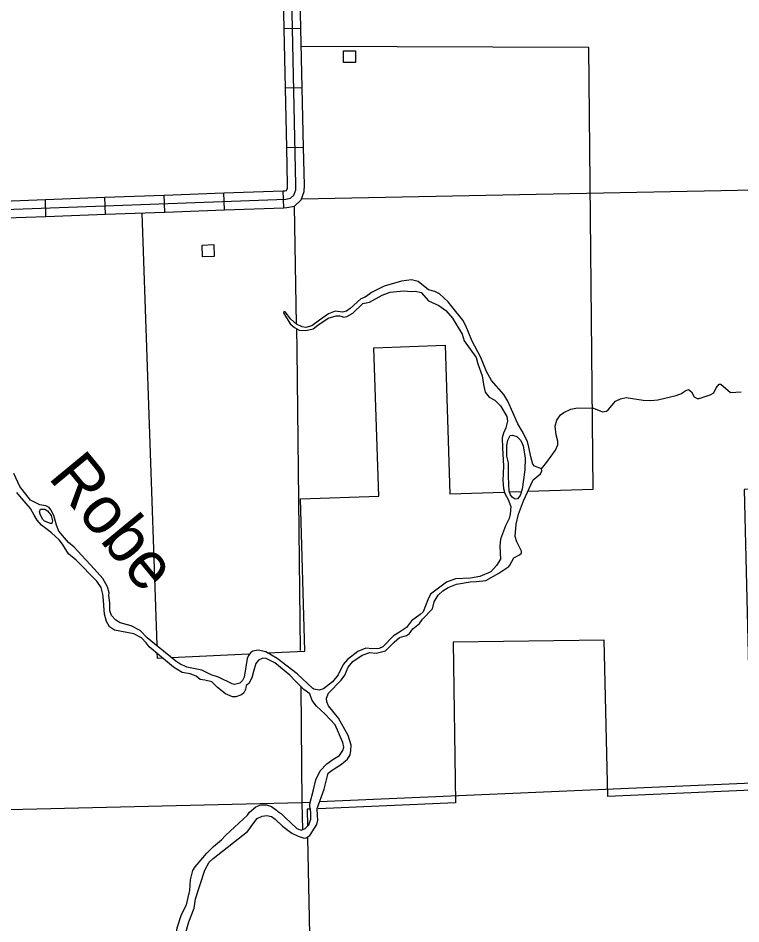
# Model space of a CAD drawing. Extents: x 1084508 to 1142749, y 1057638 to 1093403.
# Drawn here: x 1090220 to 1092233, y 1079943 to 1082464 of the extents above; entities that cross this region are included whole.
import ezdxf

# ---------------------------------------------------------------- set-up
doc = ezdxf.new("R2010")
doc.units = 0
for name, color, linetype in [('Level 32', 7, 'Continuous'), ('Level 35', 7, 'Continuous'), ('Level 5', 7, 'Continuous'), ('Level 56', 7, 'Continuous'), ('Level 7', 7, 'Continuous')]:
    doc.layers.add(name, color=color, linetype=linetype)

msp = doc.modelspace()

# ---------------------------------------------------------------- linework, layer by layer
at = {"layer": 'Level 32'}
for p, q in [((1091008, 1082435.6), (1090961, 1082434.6)), ((1091011.6, 1082270), (1090964.6, 1082268.9)), ((1091015.2, 1082104.3), (1090968.2, 1082103.2)), ((1090297.8, 1081912.2), (1090296.1, 1081959.3)), ((1090463.4, 1081918.2), (1090461.7, 1081965.3)), ((1090629, 1081924.3), (1090627.3, 1081971.3)), ((1090794.7, 1081930.3), (1090792.9, 1081977.4)), ((1090960.3, 1081936.3), (1090958.6, 1081983.4))]:
    msp.add_line(p, q, dxfattribs=at)
for points in [[(1090994, 1081999.7), (1090982.6, 1082523.3), (1090967.9, 1082952.3), (1090978.3, 1083028.7), (1090986.1, 1083044.5), (1091035.2, 1083088.7), (1091053.7, 1083101.5)], [(1090961, 1082434.6), (1090959, 1082522.7), (1090956.4, 1082600)], [(1091008, 1082435.6), (1091006.1, 1082524), (1091003.5, 1082601.6)], [(1090964.6, 1082268.9), (1090961, 1082434.6)], [(1091011.6, 1082270), (1091008, 1082435.6)], [(1090968.2, 1082103.2), (1090964.6, 1082268.9)], [(1091015.2, 1082104.3), (1091011.6, 1082270)], [(1090958.6, 1081983.4), (1090963.4, 1081983.6), (1090967.6, 1081984.4), (1090967.9, 1081984.7), (1090970, 1081990.6), (1090970.4, 1082000), (1090968.2, 1082103.2)], [(1090960.3, 1081936.3), (1090968.9, 1081936.7), (1090990.3, 1081941), (1091008.7, 1081958.6), (1091016.7, 1081981.6), (1091017.5, 1081999.4), (1091015.2, 1082104.3)], [(1090966.2, 1081960.1), (1090978.9, 1081962.7), (1090988.3, 1081971.6), (1090993.3, 1081986.1), (1090994, 1081999.7)], [(1089728.5, 1081915), (1090966.2, 1081960.1)], [(1090130.5, 1081953.2), (1090296.1, 1081959.3)], [(1090296.1, 1081959.3), (1090461.7, 1081965.3)], [(1090461.7, 1081965.3), (1090627.3, 1081971.3)], [(1090627.3, 1081971.3), (1090792.9, 1081977.4)], [(1090792.9, 1081977.4), (1090958.6, 1081983.4)], [(1090794.7, 1081930.3), (1090960.3, 1081936.3)], [(1090132.2, 1081906.2), (1090297.8, 1081912.2)], [(1090297.8, 1081912.2), (1090463.4, 1081918.2)], [(1090463.4, 1081918.2), (1090629, 1081924.3)], [(1090629, 1081924.3), (1090794.7, 1081930.3)]]:
    msp.add_lwpolyline(points, dxfattribs=at)
at = {"layer": 'Level 35'}
for points in [[(1091677.5, 1081209.9), (1091658.3, 1081216.9), (1091653.9, 1081222.1), (1091648.3, 1081243), (1091643, 1081269.9), (1091639.1, 1081286.1), (1091623.6, 1081314.7), (1091612.3, 1081334.7), (1091584, 1081397.8), (1091573.1, 1081416.2), (1091538.9, 1081455.7), (1091524.3, 1081480.3), (1091509.3, 1081519.3), (1091483.6, 1081566.4), (1091466.9, 1081607.3), (1091459, 1081623.1), (1091428.3, 1081661.1), (1091418, 1081674.8), (1091393.7, 1081697.1), (1091381.1, 1081702.8), (1091362.7, 1081708), (1091334, 1081730.6), (1091316.1, 1081735.8), (1091287.7, 1081731.7), (1091239.2, 1081717.8)], [(1091239.2, 1081717.8), (1091206.6, 1081701.7), (1091186.8, 1081687.3), (1091174.7, 1081682.6), (1091145.1, 1081655.7), (1091135, 1081648.6), (1091123.5, 1081645.2), (1091103, 1081648.1), (1091085, 1081640.9), (1091059.7, 1081623.4), (1091038.1, 1081607.9), (1091021.6, 1081603.3), (1091011.5, 1081604.7), (1090995.7, 1081612.2), (1090979.7, 1081625.7), (1090964, 1081646.4), (1090959.8, 1081647.5), (1090959.7, 1081643.7), (1090978, 1081613.6), (1090989.8, 1081603.1), (1091003.4, 1081595.9), (1091021.1, 1081594.5), (1091042.2, 1081599.2), (1091055, 1081609.3), (1091083.7, 1081628.9), (1091106.4, 1081635.6), (1091115.8, 1081635.1), (1091122.8, 1081633.2)], [(1091122.8, 1081633.2), (1091126.7, 1081631.8), (1091135.4, 1081633.5), (1091152, 1081643.1), (1091180, 1081669.3), (1091198.7, 1081673.9), (1091233.7, 1081692.6), (1091256.3, 1081701.2), (1091293.3, 1081705.1), (1091315.7, 1081703), (1091327.3, 1081704.1), (1091342.5, 1081700.7), (1091363.4, 1081677.4), (1091392, 1081664.2), (1091411.8, 1081650.6), (1091429.5, 1081629.3), (1091457.3, 1081584.2), (1091462.8, 1081566.1), (1091495.5, 1081519.3), (1091500.7, 1081501.9), (1091512.6, 1081468.4), (1091516.2, 1081443.9), (1091520.9, 1081423), (1091532.2, 1081409.3), (1091548.3, 1081400.3), (1091563.8, 1081384.9)], [(1091859, 1081370.3), (1091863.3, 1081373.4), (1091883.9, 1081397.7), (1091897.4, 1081404.6), (1091913.6, 1081408.2), (1091960.8, 1081400.6), (1091982.6, 1081399.7), (1092001.7, 1081401.8), (1092052.4, 1081413.9), (1092067.6, 1081419.7), (1092077.6, 1081426.8), (1092086.9, 1081430.3), (1092096, 1081423.8), (1092103.2, 1081410.3), (1092111.6, 1081405.3), (1092117, 1081405.2), (1092147.7, 1081415.1), (1092157.5, 1081421.3), (1092164.4, 1081435.2), (1092172.5, 1081445), (1092177.5, 1081444.9), (1092204, 1081422.1), (1092233.8, 1081423.8)], [(1091563.8, 1081384.9), (1091581.2, 1081354.8), (1091582.8, 1081341.9), (1091578.2, 1081323.7), (1091572, 1081309.2), (1091568.5, 1081295.8), (1091568.8, 1081268), (1091572, 1081217.1), (1091570.4, 1081177.2), (1091572, 1081155.2), (1091576.1, 1081140.6), (1091585.4, 1081124.3), (1091592.5, 1081104.4), (1091591, 1081083.8), (1091588.1, 1081071.1), (1091577.6, 1081051.3), (1091563.9, 1081013.5), (1091562, 1080994.4), (1091563.3, 1080958.5), (1091552.8, 1080940.1), (1091536.6, 1080922.6), (1091506.3, 1080909.5), (1091480.4, 1080905.5), (1091438.6, 1080903.3), (1091413.6, 1080893.9), (1091368.8, 1080860.9), (1091360.8, 1080844.5), (1091348.7, 1080811.7), (1091340.2, 1080803.8)], [(1091586.5, 1080937.8), (1091589.5, 1080941.7), (1091600.9, 1080962.1), (1091616.2, 1080970.4), (1091621.7, 1080975.1), (1091622.1, 1080980.5), (1091609.2, 1081006.4), (1091604.8, 1081021.3), (1091607.3, 1081055.9), (1091613.6, 1081083.3), (1091628, 1081120.5), (1091654.6, 1081178.9), (1091675.3, 1081195.9), (1091678.7, 1081203.7), (1091677.5, 1081209.9), (1091693, 1081228.3), (1091717, 1081261.9), (1091723.2, 1081276.4), (1091723.1, 1081286.5), (1091719.1, 1081304.3), (1091716.1, 1081328.4), (1091720.1, 1081345), (1091730.8, 1081360), (1091740.2, 1081366.8), (1091759.6, 1081375.6), (1091777.7, 1081379.2), (1091822.8, 1081378.5), (1091847.4, 1081368.2), (1091859, 1081370.3)], [(1091583.6, 1081289.5), (1091590.2, 1081302.2), (1091597.1, 1081303.7), (1091609.2, 1081299.6), (1091619.8, 1081288.4), (1091626.7, 1081273.9), (1091632.1, 1081239.7), (1091631, 1081206.5), (1091623.7, 1081152.9), (1091618.2, 1081135.6), (1091611.4, 1081126.1), (1091604.5, 1081125.1), (1091595.8, 1081130.7), (1091591.1, 1081137.2), (1091587.8, 1081147.1), (1091586.2, 1081188.1), (1091585.5, 1081226.2), (1091581.5, 1081245), (1091581.4, 1081274.3), (1091583.6, 1081289.5)], [(1090386.2, 1080980.3), (1090376.2, 1080991.8), (1090360.5, 1081004.7), (1090333.6, 1081035.9), (1090326.9, 1081052.7), (1090319.4, 1081079.7), (1090311.1, 1081095.2), (1090306.4, 1081101.9), (1090297.7, 1081106.2), (1090280.3, 1081108.9), (1090255.1, 1081122.6), (1090224.8, 1081160.3), (1090208.1, 1081196.5)], [(1090455.3, 1080864.8), (1090451.1, 1080879.1), (1090439.3, 1080897.2), (1090382, 1080955.1), (1090360.7, 1080972.8), (1090344.1, 1080999.5), (1090334.7, 1081012.3), (1090313, 1081031.8), (1090285.7, 1081052.3), (1090273.4, 1081066.3), (1090264.9, 1081080.4), (1090254.9, 1081099.5), (1090225.4, 1081133.5), (1090216.7, 1081143.9)], [(1090281.4, 1081083.7), (1090279.6, 1081089.9), (1090282.7, 1081097), (1090295, 1081097.3), (1090302.1, 1081092.5), (1090312.3, 1081079.3), (1090316, 1081064.8), (1090314.1, 1081057.7), (1090310.6, 1081057.3), (1090294, 1081064.1), (1090288.4, 1081069.8), (1090281.4, 1081083.7)], [(1090858.1, 1080681.6), (1090849.4, 1080629.5), (1090845.4, 1080620.1), (1090837.9, 1080612.8), (1090822.9, 1080609.6), (1090816.6, 1080610.9), (1090778.3, 1080629.7), (1090757.5, 1080636.6), (1090732.1, 1080648.7), (1090690.5, 1080657.2), (1090670.9, 1080666.7), (1090659.2, 1080674.4), (1090610.3, 1080713.8), (1090579.5, 1080739.5), (1090560.1, 1080759.5), (1090535.3, 1080772.2), (1090504.3, 1080781.2), (1090492.7, 1080788.6), (1090480.5, 1080800.9), (1090475.5, 1080814.3), (1090475.8, 1080835.7), (1090473.2, 1080856.8), (1090473.8, 1080864.4), (1090469.3, 1080881.2), (1090456.3, 1080904), (1090432.4, 1080931.6), (1090386.2, 1080980.3)], [(1091119.7, 1080621.7), (1091130.5, 1080634.8), (1091139.8, 1080657.3), (1091152.6, 1080673), (1091178.3, 1080690.6), (1091199.7, 1080698.2), (1091217.3, 1080696.5), (1091243.2, 1080702.7), (1091267.2, 1080727.5), (1091282.7, 1080739.9), (1091302, 1080745.5), (1091310.2, 1080750.9), (1091319.7, 1080764), (1091338.5, 1080778.8), (1091346.8, 1080791.1), (1091374.1, 1080819.8), (1091378.9, 1080839), (1091390, 1080857.8), (1091403, 1080870.4), (1091418, 1080879), (1091441.2, 1080888.2), (1091479, 1080895.3), (1091496.5, 1080896.1), (1091522.8, 1080899.2), (1091558.7, 1080919.5), (1091586.5, 1080937.8)], [(1090853.2, 1080595.5), (1090848.6, 1080585.9), (1090842.5, 1080580.2), (1090826.4, 1080574.8), (1090817, 1080574.6), (1090797.7, 1080583.5), (1090775.5, 1080600.8), (1090759.7, 1080617.1), (1090740.6, 1080621.3), (1090727.3, 1080623.2), (1090716.2, 1080632.2), (1090699.6, 1080638.7), (1090677.3, 1080643), (1090652.8, 1080657.7), (1090614.2, 1080690), (1090585.4, 1080714.5), (1090576.7, 1080725.5), (1090563.5, 1080738.8), (1090542.2, 1080750.4), (1090488.9, 1080760.6), (1090474.6, 1080770.1), (1090466.1, 1080784.8), (1090460.8, 1080804.8), (1090457, 1080853.8), (1090455.3, 1080864.8)], [(1091340.2, 1080803.8), (1091315.8, 1080786.9), (1091301.6, 1080768.2), (1091282.7, 1080754.7), (1091265.2, 1080744.5), (1091236.4, 1080713.8), (1091225.3, 1080709.2), (1091206.4, 1080708.6), (1091189, 1080710), (1091166.2, 1080700.8), (1091137.3, 1080679), (1091125.3, 1080664.8), (1091111.2, 1080636.4), (1091095.4, 1080617.1), (1091070.5, 1080597.6), (1091059, 1080593.3), (1091044.1, 1080596.7), (1091040.6, 1080597.8), (1090997.8, 1080638.8), (1090941.5, 1080681.3), (1090910.4, 1080700.1), (1090889.1, 1080704.5), (1090873.8, 1080701.9), (1090868, 1080698.5), (1090861.5, 1080689.7), (1090858.1, 1080681.6)], [(1091080.2, 1080388.2), (1091096.7, 1080400.3), (1091115.1, 1080411.3), (1091124.5, 1080425.3), (1091126.9, 1080434.5), (1091124.1, 1080447.7), (1091103.3, 1080497.2), (1091075.3, 1080526.5), (1091051.6, 1080548.5), (1091039.5, 1080565), (1091032.4, 1080583.3), (1091015.8, 1080595.4), (1090992.5, 1080618.3), (1090976.6, 1080635.6), (1090935.4, 1080669.7), (1090910.6, 1080681.2), (1090901.4, 1080682.7), (1090889.7, 1080677.1), (1090882.3, 1080667.3), (1090875.4, 1080645.5), (1090871.2, 1080627.6), (1090863.1, 1080612.4), (1090855.8, 1080606.4), (1090853.2, 1080595.5)], [(1090865.3, 1080208), (1090871.5, 1080217.1), (1090885.7, 1080236), (1090899.6, 1080243), (1090913.1, 1080244.2), (1090925.5, 1080241.6), (1090936.2, 1080234.2), (1090956.6, 1080214.7), (1090982.3, 1080195), (1091000.3, 1080186.7), (1091017.2, 1080181.8), (1091022.8, 1080182.4), (1091032.6, 1080188.5), (1091052, 1080219.4), (1091055.2, 1080231.2), (1091054, 1080245), (1091053.1, 1080264.2), (1091073, 1080317.8), (1091083.9, 1080362.2), (1091094.6, 1080370.9), (1091120.5, 1080387.9), (1091137.5, 1080401.3), (1091144.9, 1080413.6), (1091147.2, 1080425.1), (1091147.4, 1080440.2), (1091139.3, 1080467.6), (1091112.9, 1080515.6), (1091084.9, 1080549.7), (1091079.7, 1080561.4), (1091079.5, 1080570.9), (1091084.9, 1080584.7), (1091119.7, 1080621.7)], [(1090696.6, 1080028.9), (1090698.4, 1080036.2), (1090700.3, 1080065.3), (1090706.9, 1080091.8), (1090713.1, 1080102.2), (1090745.4, 1080140), (1090764.1, 1080157.9), (1090786.5, 1080176.6), (1090798.5, 1080190.1), (1090858.6, 1080245.5), (1090864.8, 1080254), (1090881.8, 1080268.7), (1090896, 1080274.4), (1090911.7, 1080274.5), (1090925.7, 1080270.1), (1090940.1, 1080259.7), (1090942.7, 1080256.3), (1090953.7, 1080249.2), (1090964, 1080239), (1090996.8, 1080208.3), (1091008.7, 1080203.8), (1091019.8, 1080208.7), (1091029.4, 1080219), (1091035, 1080234), (1091035.4, 1080253.3), (1091032.7, 1080270.5), (1091032.4, 1080277.5), (1091043.2, 1080316.5), (1091049.5, 1080343.9), (1091061, 1080368.7), (1091080.2, 1080388.2)], [(1090685.5, 1079912.5), (1090696.1, 1079948.4), (1090710.4, 1079986.3), (1090714.6, 1080013), (1090740.2, 1080092.7), (1090752.2, 1080114.7), (1090763, 1080125.3), (1090859.1, 1080200.1), (1090865.3, 1080208)], [(1090926.4, 1079486.2), (1090931.7, 1079560.3), (1090926.2, 1079576.5), (1090910.7, 1079600), (1090896.2, 1079614.2), (1090867.8, 1079629.3), (1090857.1, 1079637.7), (1090845.7, 1079645.7), (1090801.2, 1079684.3), (1090731.8, 1079722.8), (1090721.2, 1079733.4), (1090709.7, 1079750.8), (1090690.2, 1079806.7), (1090666.2, 1079843.2), (1090662.3, 1079861), (1090658.2, 1079896.8), (1090663.5, 1079931.7), (1090675.7, 1079968.9), (1090688.9, 1079995.7), (1090696.6, 1080028.9)]]:
    msp.add_lwpolyline(points, dxfattribs=at)
at = {"layer": 'Level 5'}
msp.add_line((1090989.4, 1081940.8), (1090994.9, 1081612.6), dxfattribs=at)
for points in [[(1091009.6, 1081961.4), (1092643.9, 1081993.6)], [(1090995.1, 1081600.3), (1090996.1, 1081540.6), (1091005.9, 1080704.1)], [(1091007.3, 1080603.7), (1091007.3, 1080602), (1091010.2, 1080280.2), (1091012, 1080205.8), (1091012, 1080205.7)], [(1092673.9, 1080352.1), (1091059.9, 1080282.4)], [(1091033.4, 1080281.2), (1091010.2, 1080280.2), (1090194.1, 1080260.2)]]:
    msp.add_lwpolyline(points, dxfattribs=at)
at = {"layer": 'Level 56'}
for points in [[(1091126.6, 1082340.3), (1091126.6, 1082373), (1091159.4, 1082373), (1091159.4, 1082340.3)], [(1090733.8, 1081799.9), (1090732.8, 1081832.5), (1090765.5, 1081833.6), (1090766.6, 1081800.9)]]:
    msp.add_lwpolyline(points, close=True, dxfattribs=at)
at = {"layer": 'Level 7'}
for points in [[(1091640, 1081147.2), (1091821.6, 1081153.4), (1091809.7, 1082382.5), (1091008.2, 1082384.8)], [(1090565.1, 1081921.4), (1090606.3, 1080718.3)], [(1090913.8, 1080697.3), (1091018.6, 1080702.2), (1091018.6, 1080702.6), (1091006.2, 1081125.7), (1091224.5, 1081133.1), (1091210.9, 1081546.7), (1091409.6, 1081554.2), (1091422.2, 1081139.8), (1091573.6, 1081145)], [(1092645.5, 1081168.5), (1092645.5, 1081162.5), (1092242, 1081152.1), (1092262.5, 1080315.1), (1091862.6, 1080297.9), (1091852.5, 1080732.2), (1091432, 1080727.2), (1091438.2, 1080279.7), (1091055.7, 1080263.3)], [(1091589.4, 1081145.5), (1091621.1, 1081146.6)], [(1090607, 1080697.8), (1090607.5, 1080683), (1090623.2, 1080683.7)], [(1090646.9, 1080684.8), (1090863.2, 1080694.9)], [(1091035.1, 1080262.4), (1091025.2, 1080262), (1091026, 1080214.7)], [(1091026.6, 1080183.1), (1091032.3, 1079869.3), (1091434.1, 1079883.9), (1091446.7, 1079468.2), (1091038.2, 1079455.7), (1091047.3, 1079045), (1090611.1, 1079030.9), (1090614.3, 1078939.2)]]:
    msp.add_lwpolyline(points, dxfattribs=at)

# ---------------------------------------------------------------- texts
at = {"layer": 'Level 35'}
msp.add_text('Robe', height=132.58, rotation=309.511, dxfattribs=at).set_placement((1090301.6, 1081185.3))

doc.saveas('drawing.dxf')
